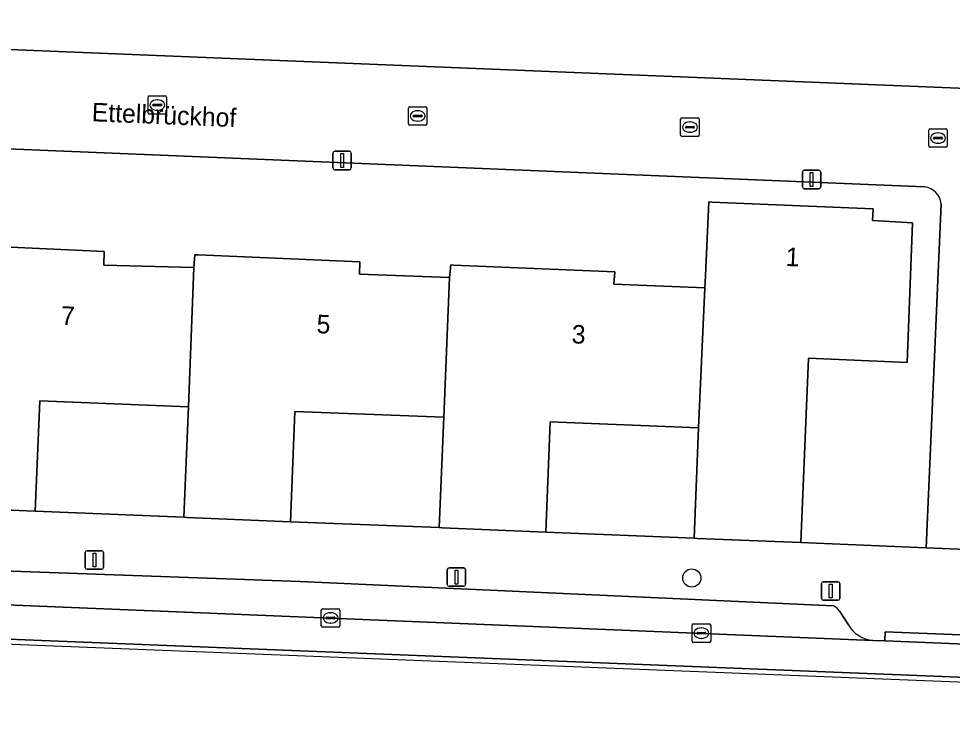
# Model space of a CAD drawing. Extents: x 160786 to 161429, y 386828 to 387485.
# Drawn here: x 161177.6 to 161228, y 386895.7 to 386934 of the extents above; entities that cross this region are included whole.
import ezdxf

# ---------------------------------------------------------------- set-up
doc = ezdxf.new("R2010")
doc.units = 0
for name, color, linetype in [('IMGEO_Boom', 7, 'Continuous'), ('IMGEO_Erf', 7, 'Continuous'), ('IMGEO_Kolk', 7, 'Continuous'), ('IMGEO_Lichtmast', 7, 'Continuous'), ('IMGEO_Openbare_ruimte_label', 7, 'Continuous'), ('IMGEO_Pand', 7, 'Continuous'), ('IMGEO_Pand_nummerreeks', 7, 'Continuous'), ('IMGEO_Parkeervlak_open', 7, 'Continuous'), ('IMGEO_Rijbaan_lokaal_gesloten', 7, 'Continuous'), ('IMGEO_Voetpad_open', 7, 'Continuous')]:
    doc.layers.add(name, color=color, linetype=linetype)

msp = doc.modelspace()

# ---------------------------------------------------------------- linework, layer by layer
at = {"layer": 'IMGEO_Boom'}
msp.add_circle((161213.924, 386903.837), 0.489, dxfattribs=at)
at = {"layer": 'IMGEO_Erf'}
for points in [[(161159.93, 386937.679), (161159.797, 386933.081), (161228.777, 386930.274)], [(161226.501, 386924.954), (161162.187, 386927.617)], [(161173.621, 386921.87), (161182.182, 386921.468), (161182.164, 386920.731), (161187.022, 386920.605), (161187.08, 386921.289), (161187.278, 386921.281), (161195.994, 386920.907), (161195.966, 386920.25), (161200.842, 386920.057), (161200.909, 386920.739), (161201.052, 386920.733), (161209.772, 386920.362), (161209.716, 386919.702), (161214.632, 386919.507), (161214.661, 386920.153), (161214.838, 386924.146), (161215.008, 386924.139), (161223.723, 386923.769), (161223.681, 386923.138), (161225.845, 386923.021), (161225.555, 386915.471), (161220.23, 386915.714), (161219.809, 386905.751), (161226.578, 386905.472), (161227.385, 386924.042)]]:
    msp.add_lwpolyline(points, dxfattribs=at)
for points in [[(161178.458, 386907.447), (161186.492, 386907.118), (161186.74, 386913.083), (161178.706, 386913.412)], [(161192.24, 386906.863), (161200.275, 386906.557), (161200.523, 386912.522), (161192.488, 386912.828)], [(161206.033, 386906.311), (161214.044, 386905.981), (161214.292, 386911.946), (161206.281, 386912.276)]]:
    msp.add_lwpolyline(points, close=True, dxfattribs=at)
msp.add_arc((161226.387, 386923.959), 1.002, 4.7668, 83.4468, dxfattribs=at)
at = {"layer": 'IMGEO_Kolk'}
for p, q in [((161184.551, 386928.95), (161184.551, 386929.802)), ((161184.626, 386929.876), (161185.478, 386929.876)), ((161184.853, 386929.419), (161185.251, 386929.419)), ((161185.039, 386929.656), (161185.064, 386929.656)), ((161185.552, 386929.802), (161185.552, 386928.95)), ((161184.81, 386929.37), (161184.81, 386929.382)), ((161185.248, 386929.333), (161184.85, 386929.333)), ((161185.062, 386929.096), (161185.037, 386929.096)), ((161185.294, 386929.382), (161185.294, 386929.37)), ((161198.613, 386928.36), (161198.613, 386929.212)), ((161198.688, 386929.286), (161199.54, 386929.286)), ((161199.101, 386929.066), (161199.126, 386929.066)), ((161199.614, 386929.212), (161199.614, 386928.36)), ((161185.478, 386928.876), (161184.626, 386928.876)), ((161198.872, 386928.78), (161198.872, 386928.792)), ((161199.31, 386928.743), (161198.912, 386928.743)), ((161198.915, 386928.829), (161199.313, 386928.829)), ((161199.124, 386928.506), (161199.099, 386928.506)), ((161199.356, 386928.792), (161199.356, 386928.78)), ((161213.321, 386927.757), (161213.321, 386928.609)), ((161213.396, 386928.683), (161214.248, 386928.683)), ((161213.809, 386928.463), (161213.834, 386928.463)), ((161214.322, 386928.609), (161214.322, 386927.757)), ((161199.54, 386928.286), (161198.688, 386928.286)), ((161213.58, 386928.177), (161213.58, 386928.189)), ((161214.018, 386928.14), (161213.62, 386928.14)), ((161213.623, 386928.226), (161214.021, 386928.226)), ((161213.832, 386927.903), (161213.807, 386927.903)), ((161214.064, 386928.189), (161214.064, 386928.177)), ((161226.721, 386927.167), (161226.721, 386928.019)), ((161226.796, 386928.093), (161227.648, 386928.093)), ((161227.209, 386927.873), (161227.234, 386927.873)), ((161227.722, 386928.019), (161227.722, 386927.167)), ((161214.248, 386927.683), (161213.396, 386927.683)), ((161226.98, 386927.587), (161226.98, 386927.599)), ((161227.418, 386927.55), (161227.02, 386927.55)), ((161227.023, 386927.636), (161227.421, 386927.636)), ((161227.464, 386927.599), (161227.464, 386927.587)), ((161227.648, 386927.093), (161226.796, 386927.093)), ((161227.232, 386927.313), (161227.207, 386927.313)), ((161193.987, 386902.181), (161194.839, 386902.181)), ((161193.912, 386901.255), (161193.912, 386902.107)), ((161194.171, 386901.675), (161194.171, 386901.687)), ((161194.214, 386901.724), (161194.612, 386901.724)), ((161194.4, 386901.961), (161194.425, 386901.961)), ((161194.655, 386901.687), (161194.655, 386901.675)), ((161194.913, 386902.107), (161194.913, 386901.255)), ((161194.839, 386901.181), (161193.987, 386901.181)), ((161194.609, 386901.638), (161194.211, 386901.638)), ((161194.423, 386901.401), (161194.398, 386901.401)), ((161213.944, 386900.433), (161213.944, 386901.285)), ((161214.019, 386901.359), (161214.871, 386901.359)), ((161214.945, 386901.285), (161214.945, 386900.433)), ((161214.203, 386900.853), (161214.203, 386900.865)), ((161214.641, 386900.816), (161214.243, 386900.816)), ((161214.246, 386900.902), (161214.644, 386900.902)), ((161214.432, 386901.139), (161214.457, 386901.139)), ((161214.687, 386900.865), (161214.687, 386900.853)), ((161214.871, 386900.359), (161214.019, 386900.359)), ((161214.455, 386900.579), (161214.43, 386900.579))]:
    msp.add_line(p, q, dxfattribs=at)
for points in [[(161184.551, 386928.95), (161184.551, 386929.802)], [(161184.626, 386929.876), (161185.478, 386929.876)], [(161185.552, 386929.802), (161185.552, 386928.95)], [(161198.613, 386928.36), (161198.613, 386929.212)], [(161198.688, 386929.286), (161199.54, 386929.286)], [(161199.614, 386929.212), (161199.614, 386928.36)], [(161185.478, 386928.876), (161184.626, 386928.876)], [(161213.321, 386927.757), (161213.321, 386928.609)], [(161213.396, 386928.683), (161214.248, 386928.683)], [(161214.322, 386928.609), (161214.322, 386927.757)], [(161199.54, 386928.286), (161198.688, 386928.286)], [(161226.721, 386927.167), (161226.721, 386928.019)], [(161226.796, 386928.093), (161227.648, 386928.093)], [(161227.722, 386928.019), (161227.722, 386927.167)], [(161214.248, 386927.683), (161213.396, 386927.683)], [(161227.648, 386927.093), (161226.796, 386927.093)], [(161193.987, 386902.181), (161194.839, 386902.181)], [(161193.912, 386901.255), (161193.912, 386902.107)], [(161194.913, 386902.107), (161194.913, 386901.255)], [(161194.839, 386901.181), (161193.987, 386901.181)], [(161213.944, 386900.433), (161213.944, 386901.285)], [(161214.019, 386901.359), (161214.871, 386901.359)], [(161214.945, 386901.285), (161214.945, 386900.433)], [(161214.871, 386900.359), (161214.019, 386900.359)]]:
    msp.add_lwpolyline(points, dxfattribs=at)
for centre, radius, start, end in [((161184.628, 386929.8), 0.0765, 91.552, 178.448), ((161184.628, 386929.8), 0.0765, 91.552, 178.448), ((161184.85, 386929.379), 0.0403, 85.8775, 175.7526), ((161185.255, 386929.381), 0.0386, 1.7309, 96.639), ((161185.476, 386929.8), 0.0765, 1.552, 88.448), ((161185.476, 386929.8), 0.0765, 1.552, 88.448), ((161184.628, 386928.952), 0.0765, 181.552, 268.448), ((161184.628, 386928.952), 0.0765, 181.552, 268.448), ((161184.847, 386929.369), 0.0366, 178.938, 274.7102), ((161185.251, 386929.376), 0.043, 264.8664, 352.4533), ((161185.476, 386928.952), 0.0765, 271.552, 358.448), ((161185.476, 386928.952), 0.0765, 271.552, 358.448), ((161198.69, 386929.21), 0.0765, 91.552, 178.448), ((161198.69, 386929.21), 0.0765, 91.552, 178.448), ((161199.538, 386929.21), 0.0765, 1.552, 88.448), ((161199.538, 386929.21), 0.0765, 1.552, 88.448), ((161198.912, 386928.789), 0.0403, 85.8775, 175.7526), ((161198.909, 386928.779), 0.0366, 178.938, 274.7102), ((161199.313, 386928.786), 0.043, 264.8664, 352.4533), ((161199.317, 386928.791), 0.0386, 1.7309, 96.639), ((161213.398, 386928.607), 0.0765, 91.552, 178.448), ((161213.398, 386928.607), 0.0765, 91.552, 178.448), ((161214.246, 386928.607), 0.0765, 1.552, 88.448), ((161214.246, 386928.607), 0.0765, 1.552, 88.448), ((161198.69, 386928.362), 0.0765, 181.552, 268.448), ((161198.69, 386928.362), 0.0765, 181.552, 268.448), ((161199.538, 386928.362), 0.0765, 271.552, 358.448), ((161199.538, 386928.362), 0.0765, 271.552, 358.448), ((161213.62, 386928.186), 0.0403, 85.8775, 175.7526), ((161213.617, 386928.176), 0.0366, 178.938, 274.7102), ((161214.021, 386928.183), 0.043, 264.8664, 352.4533), ((161214.025, 386928.188), 0.0386, 1.7309, 96.639), ((161226.798, 386928.017), 0.0765, 91.552, 178.448), ((161226.798, 386928.017), 0.0765, 91.552, 178.448), ((161227.646, 386928.017), 0.0765, 1.552, 88.448), ((161227.646, 386928.017), 0.0765, 1.552, 88.448), ((161213.398, 386927.759), 0.0765, 181.552, 268.448), ((161213.398, 386927.759), 0.0765, 181.552, 268.448), ((161214.246, 386927.759), 0.0765, 271.552, 358.448), ((161214.246, 386927.759), 0.0765, 271.552, 358.448), ((161227.02, 386927.596), 0.0403, 85.8775, 175.7526), ((161227.017, 386927.586), 0.0366, 178.938, 274.7102), ((161227.421, 386927.593), 0.043, 264.8664, 352.4533), ((161227.425, 386927.598), 0.0386, 1.7309, 96.639), ((161226.798, 386927.169), 0.0765, 181.552, 268.448), ((161226.798, 386927.169), 0.0765, 181.552, 268.448), ((161227.646, 386927.169), 0.0765, 271.552, 358.448), ((161227.646, 386927.169), 0.0765, 271.552, 358.448), ((161193.989, 386902.105), 0.0765, 91.552, 178.448), ((161193.989, 386902.105), 0.0765, 91.552, 178.448), ((161194.837, 386902.105), 0.0765, 1.552, 88.448), ((161194.837, 386902.105), 0.0765, 1.552, 88.448), ((161194.211, 386901.684), 0.0403, 85.8775, 175.7526), ((161194.208, 386901.674), 0.0366, 178.938, 274.7102), ((161194.612, 386901.681), 0.043, 264.8664, 352.4533), ((161194.616, 386901.686), 0.0386, 1.7309, 96.639), ((161193.989, 386901.257), 0.0765, 181.552, 268.448), ((161193.989, 386901.257), 0.0765, 181.552, 268.448), ((161194.837, 386901.257), 0.0765, 271.552, 358.448), ((161194.837, 386901.257), 0.0765, 271.552, 358.448), ((161214.021, 386901.283), 0.0765, 91.552, 178.448), ((161214.021, 386901.283), 0.0765, 91.552, 178.448), ((161214.869, 386901.283), 0.0765, 1.552, 88.448), ((161214.869, 386901.283), 0.0765, 1.552, 88.448), ((161214.243, 386900.862), 0.0403, 85.8775, 175.7526), ((161214.24, 386900.852), 0.0366, 178.938, 274.7102), ((161214.644, 386900.859), 0.043, 264.8664, 352.4533), ((161214.648, 386900.864), 0.0386, 1.7309, 96.639), ((161214.021, 386900.435), 0.0765, 181.552, 268.448), ((161214.021, 386900.435), 0.0765, 181.552, 268.448), ((161214.869, 386900.435), 0.0765, 271.552, 358.448), ((161214.869, 386900.435), 0.0765, 271.552, 358.448)]:
    msp.add_arc(centre, radius, start, end, dxfattribs=at)
for centre, major_axis, ratio, start_param, end_param in [((161185.038, 386929.376), (-0.387, 0.002), 0.722429, 4.712389, 7.853982), ((161185.063, 386929.376), (-0.39, 0.002), 0.717154, 1.570796, 4.712389), ((161199.1, 386928.786), (-0.387, 0.002), 0.722429, 4.712389, 7.853982), ((161199.125, 386928.786), (-0.39, 0.002), 0.717154, 1.570796, 4.712389), ((161213.808, 386928.183), (-0.387, 0.002), 0.722429, 4.712389, 7.853982), ((161213.833, 386928.183), (-0.39, 0.002), 0.717154, 1.570796, 4.712389), ((161227.208, 386927.593), (-0.387, 0.002), 0.722429, 4.712389, 7.853982), ((161227.233, 386927.593), (-0.39, 0.002), 0.717154, 1.570796, 4.712389), ((161194.399, 386901.681), (-0.387, 0.002), 0.722429, 4.712389, 7.853982), ((161194.424, 386901.681), (-0.39, 0.002), 0.717154, 1.570796, 4.712389), ((161214.431, 386900.859), (-0.387, 0.002), 0.722429, 4.712389, 7.853982), ((161214.456, 386900.859), (-0.39, 0.002), 0.717154, 1.570796, 4.712389)]:
    msp.add_ellipse(centre, major_axis=major_axis, ratio=ratio, start_param=start_param, end_param=end_param, dxfattribs=at)
at = {"layer": 'IMGEO_Lichtmast'}
for p, q in [((161194.641, 386926.88), (161195.431, 386926.88)), ((161195.431, 386926.88), (161194.641, 386926.88)), ((161194.541, 386925.98), (161194.541, 386926.78)), ((161194.541, 386926.78), (161194.541, 386925.98)), ((161195.531, 386926.78), (161195.531, 386925.98)), ((161195.531, 386925.98), (161195.531, 386926.78)), ((161195.431, 386925.88), (161194.641, 386925.88)), ((161194.641, 386925.88), (161195.431, 386925.88)), ((161219.898, 386924.954), (161219.898, 386925.754)), ((161219.898, 386925.754), (161219.898, 386924.954)), ((161219.998, 386925.854), (161220.788, 386925.854)), ((161220.788, 386925.854), (161219.998, 386925.854)), ((161220.888, 386925.754), (161220.888, 386924.954)), ((161220.888, 386924.954), (161220.888, 386925.754)), ((161220.788, 386924.854), (161219.998, 386924.854)), ((161219.998, 386924.854), (161220.788, 386924.854)), ((161181.165, 386904.409), (161181.165, 386905.209)), ((161181.165, 386905.209), (161181.165, 386904.409)), ((161181.265, 386905.309), (161182.055, 386905.309)), ((161182.055, 386905.309), (161181.265, 386905.309)), ((161182.155, 386905.209), (161182.155, 386904.409)), ((161182.155, 386904.409), (161182.155, 386905.209)), ((161182.055, 386904.309), (161181.265, 386904.309)), ((161181.265, 386904.309), (161182.055, 386904.309)), ((161200.717, 386903.488), (161200.717, 386904.288)), ((161200.717, 386904.288), (161200.717, 386903.488)), ((161200.817, 386904.388), (161201.607, 386904.388)), ((161201.607, 386904.388), (161200.817, 386904.388)), ((161201.707, 386904.288), (161201.707, 386903.488)), ((161201.707, 386903.488), (161201.707, 386904.288)), ((161201.607, 386903.388), (161200.817, 386903.388)), ((161200.817, 386903.388), (161201.607, 386903.388)), ((161220.928, 386902.737), (161220.928, 386903.537)), ((161220.928, 386903.537), (161220.928, 386902.737)), ((161221.028, 386903.637), (161221.818, 386903.637)), ((161221.818, 386903.637), (161221.028, 386903.637)), ((161221.918, 386903.537), (161221.918, 386902.737)), ((161221.918, 386902.737), (161221.918, 386903.537)), ((161221.818, 386902.637), (161221.028, 386902.637)), ((161221.028, 386902.637), (161221.818, 386902.637))]:
    msp.add_line(p, q, dxfattribs=at)
for points in [[(161194.961, 386926.755), (161195.111, 386926.755), (161195.111, 386926.005), (161194.961, 386926.005), (161194.961, 386926.755)], [(161220.318, 386925.729), (161220.468, 386925.729), (161220.468, 386924.979), (161220.318, 386924.979), (161220.318, 386925.729)], [(161181.585, 386905.184), (161181.735, 386905.184), (161181.735, 386904.434), (161181.585, 386904.434), (161181.585, 386905.184)], [(161201.137, 386904.263), (161201.287, 386904.263), (161201.287, 386903.513), (161201.137, 386903.513), (161201.137, 386904.263)], [(161221.348, 386903.512), (161221.498, 386903.512), (161221.498, 386902.762), (161221.348, 386902.762), (161221.348, 386903.512)]]:
    msp.add_lwpolyline(points, dxfattribs=at)
for centre, start, end in [((161194.641, 386926.78), 90, 180), ((161194.641, 386926.78), 90, 180), ((161195.431, 386926.78), 0, 90), ((161195.431, 386926.78), 360, 90), ((161194.641, 386925.98), 180, 270), ((161194.641, 386925.98), 180, 270), ((161195.431, 386925.98), 270, 0), ((161195.431, 386925.98), 270, 0), ((161219.998, 386925.754), 90, 180), ((161219.998, 386925.754), 90, 180), ((161220.788, 386925.754), 0, 90), ((161220.788, 386925.754), 360, 90), ((161219.998, 386924.954), 180, 270), ((161219.998, 386924.954), 180, 270), ((161220.788, 386924.954), 270, 0), ((161220.788, 386924.954), 270, 0), ((161181.265, 386905.209), 90, 180), ((161181.265, 386905.209), 90, 180), ((161182.055, 386905.209), 0, 90), ((161182.055, 386905.209), 360, 90), ((161181.265, 386904.409), 180, 270), ((161181.265, 386904.409), 180, 270), ((161182.055, 386904.409), 270, 0), ((161182.055, 386904.409), 270, 0), ((161200.817, 386904.288), 90, 180), ((161200.817, 386904.288), 90, 180), ((161201.607, 386904.288), 0, 90), ((161201.607, 386904.288), 360, 90), ((161200.817, 386903.488), 180, 270), ((161200.817, 386903.488), 180, 270), ((161201.607, 386903.488), 270, 0), ((161201.607, 386903.488), 270, 0), ((161221.028, 386903.537), 90, 180), ((161221.028, 386903.537), 90, 180), ((161221.818, 386903.537), 0, 90), ((161221.818, 386903.537), 360, 90), ((161221.028, 386902.737), 180, 270), ((161221.028, 386902.737), 180, 270), ((161221.818, 386902.737), 270, 0), ((161221.818, 386902.737), 270, 0)]:
    msp.add_arc(centre, 0.1, start, end, dxfattribs=at)
at = {"layer": 'IMGEO_Pand'}
for points in [[(161214.632, 386919.507), (161214.292, 386911.946), (161214.044, 386905.981), (161214.226, 386905.974), (161219.809, 386905.751), (161220.23, 386915.714), (161225.555, 386915.471), (161225.845, 386923.021), (161223.681, 386923.138), (161223.723, 386923.769), (161215.008, 386924.139), (161214.838, 386924.146), (161214.661, 386920.153)], [(161187.022, 386920.605), (161182.164, 386920.731), (161182.182, 386921.468), (161173.621, 386921.87), (161173.307, 386921.885), (161173.128, 386917.649), (161173.005, 386914.747), (161172.707, 386907.686), (161172.881, 386907.679), (161178.458, 386907.447), (161178.706, 386913.412), (161186.74, 386913.083)], [(161186.492, 386907.118), (161186.669, 386907.11), (161192.24, 386906.863), (161192.488, 386912.828), (161200.523, 386912.522), (161200.842, 386920.057), (161195.966, 386920.25), (161195.994, 386920.907), (161187.278, 386921.281), (161187.08, 386921.289), (161187.022, 386920.605), (161186.74, 386913.083)], [(161209.716, 386919.702), (161209.772, 386920.362), (161201.052, 386920.733), (161200.909, 386920.739), (161200.842, 386920.057), (161200.523, 386912.522), (161200.275, 386906.557), (161200.447, 386906.55), (161206.033, 386906.311), (161206.281, 386912.276), (161214.292, 386911.946), (161214.632, 386919.507)]]:
    msp.add_lwpolyline(points, close=True, dxfattribs=at)
at = {"layer": 'IMGEO_Parkeervlak_open'}
for points in [[(161221.57, 386902.335), (161192.762, 386903.644), (161174.681, 386904.304), (161165.97, 386904.699)], [(161162.46, 386902.982), (161223.699, 386900.466)], [(161222.38, 386901.304), (161221.913, 386902.02)]]:
    msp.add_lwpolyline(points, dxfattribs=at)
for centre, radius, start, end in [((161221.325, 386901.724), 0.659, 26.7295, 68.1437), ((161223.863, 386902.182), 1.724, 210.6168, 264.5252)]:
    msp.add_arc(centre, radius, start, end, dxfattribs=at)
at = {"layer": 'IMGEO_Rijbaan_lokaal_gesloten'}
msp.add_lwpolyline([(161234.905, 386900.003), (161234.751, 386900.009), (161224.348, 386900.439), (161223.699, 386900.466), (161162.46, 386902.982), (161161.944, 386903.003), (161151.67, 386903.416), (161135.502, 386904.066), (161131.97, 386904.208), (161128.825, 386904.334), (161123.496, 386904.504), (161123.39, 386902.685), (161248.174, 386897.682), (161280.349, 386896.413), (161280.429, 386898.124), (161278.893, 386898.183), (161277.3, 386898.249), (161276.855, 386898.267)], close=True, dxfattribs=at)
msp.add_lwpolyline([(161281.403, 386896.371), (161280.349, 386896.413), (161248.174, 386897.682), (161123.39, 386902.685), (161123.374, 386902.409), (161291.165, 386895.721)], dxfattribs=at)
at = {"layer": 'IMGEO_Voetpad_open'}
for points in [[(161227.385, 386924.042), (161226.578, 386905.472), (161232.717, 386905.215), (161233.768, 386930.072), (161228.777, 386930.274), (161159.797, 386933.081), (161155.076, 386933.218), (161154.675, 386933.229), (161154.657, 386932.767), (161154.583, 386930.916), (161153.688, 386908.393), (161154.016, 386908.384), (161160.441, 386908.186), (161161.223, 386926.739)], [(161162.187, 386927.617), (161226.501, 386924.954)], [(161178.458, 386907.447), (161172.881, 386907.679), (161172.707, 386907.686), (161167.669, 386907.897), (161161.921, 386908.14), (161160.441, 386908.186), (161154.016, 386908.384), (161153.688, 386908.393), (161151.569, 386908.451), (161151.389, 386908.43), (161144.348, 386908.66), (161144.206, 386908.675), (161143.967, 386908.672), (161143.729, 386908.68), (161143.492, 386908.694), (161122.06, 386909.472)], [(161285.519, 386903.217), (161276.289, 386903.527), (161256.202, 386904.203), (161249.934, 386904.471), (161246.861, 386904.602), (161237.836, 386904.988), (161235.128, 386905.104), (161232.717, 386905.215), (161226.578, 386905.472), (161219.809, 386905.751), (161214.226, 386905.974), (161214.044, 386905.981), (161206.033, 386906.311), (161200.447, 386906.55), (161200.275, 386906.557), (161192.24, 386906.863), (161186.669, 386907.11), (161186.492, 386907.118), (161178.458, 386907.447)], [(161165.97, 386904.699), (161174.681, 386904.304), (161192.762, 386903.644), (161221.57, 386902.335)], [(161221.913, 386902.02), (161222.38, 386901.304)], [(161223.699, 386900.466), (161224.348, 386900.439), (161224.368, 386900.938), (161234.771, 386900.508), (161234.751, 386900.009), (161234.905, 386900.003)]]:
    msp.add_lwpolyline(points, dxfattribs=at)
msp.add_lwpolyline([(161234.751, 386900.009), (161234.771, 386900.508), (161224.368, 386900.938), (161224.348, 386900.439)], close=True, dxfattribs=at)
for centre, radius, start, end in [((161226.387, 386923.959), 1.002, 4.7668, 83.4468), ((161221.325, 386901.724), 0.659, 26.7295, 68.1437), ((161223.863, 386902.182), 1.724, 210.6168, 264.5252)]:
    msp.add_arc(centre, radius, start, end, dxfattribs=at)

# ---------------------------------------------------------------- texts
at = {"layer": 'IMGEO_Openbare_ruimte_label'}
msp.add_text('Ettelbrückhof', height=1, rotation=357.6498, dxfattribs=at).set_placement((161181.499, 386928.502))
at = {"layer": 'IMGEO_Pand_nummerreeks'}
for s, rotation, p in [('1', 357.5703, (161218.981, 386920.687)), ('7', 358.516, (161179.846, 386917.51)), ('5', 357.7333, (161193.641, 386917.059)), ('3', 357.7285, (161207.422, 386916.51))]:
    msp.add_text(s, height=1, rotation=rotation, dxfattribs=at).set_placement(p)

doc.saveas('drawing.dxf')
